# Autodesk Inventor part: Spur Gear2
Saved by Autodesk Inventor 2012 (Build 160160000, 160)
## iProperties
Created: 2011-12
Part Number: Spur Gear2
Material: Steel
Document SubType Name: Modeling
Designer: Admin
Categories: <?xml version="1.0" encoding="UTF-16"?> <MemberInstance><Categories><FamilyTemplate><FamilyTemplateParameter ValueType="xs:double" Id="1" ObjectReferenceKey="da
Density: 1 g/cm^3
CustomPartVersion: 1
Author: Admin
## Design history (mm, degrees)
sketch "Sketch1"
  geometry: C1 r 42 at (0, 0)
  constraints: 1 centre point
  dimensions: "d0" = 84 diameter of C1 (= da_da)
extrude "Extrusion1" new body sketch "Sketch1" distance "d1" = 35 (= da_b); taper "d2" = 0 deg
workplane "Work Plane2"
sketch "Sketch2"
  geometry: C1 r 42 at (0, 0) reference; C2 r 40 at (0, 0)
  constraints: 1 centre point, 1 coincident
  dimensions: "d3" = 80 diameter of C2 (= da_dw)
feature "Pitch Diameter" sketch "Sketch2" dims "d4" = 10, "d5" = 0
workplane "Work Plane8"
workplane "Work Plane9"
feature "Spur Gear" dims "da_b" = 35, "da_d" = 80, "da_aw" = 80, "da_da" = 84, "da_df" = 75, "da_dw" = 80, angle "da_beta" = 0 deg, "da_lefttooth" = 0, "da_righttooth" = 0
body "Solid1"
body "Srf1"
other parameters: "d17" = 0, "d34" = 4.5 deg (computed from da_z), "d39" = 0, "d41" = 0, "d47" = 0, "d48" = 0
